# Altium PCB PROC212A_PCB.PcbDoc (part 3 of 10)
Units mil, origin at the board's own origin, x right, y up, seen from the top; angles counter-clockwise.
Board outline 3032.48 x 3598.78 mil, 4 copper layers (Top Layer, L2_GND1, L3_PWR1, Bottom Layer), stack 60.58 mil thick; 432 components, 310 nets, 7775 pads, 1236 vias.
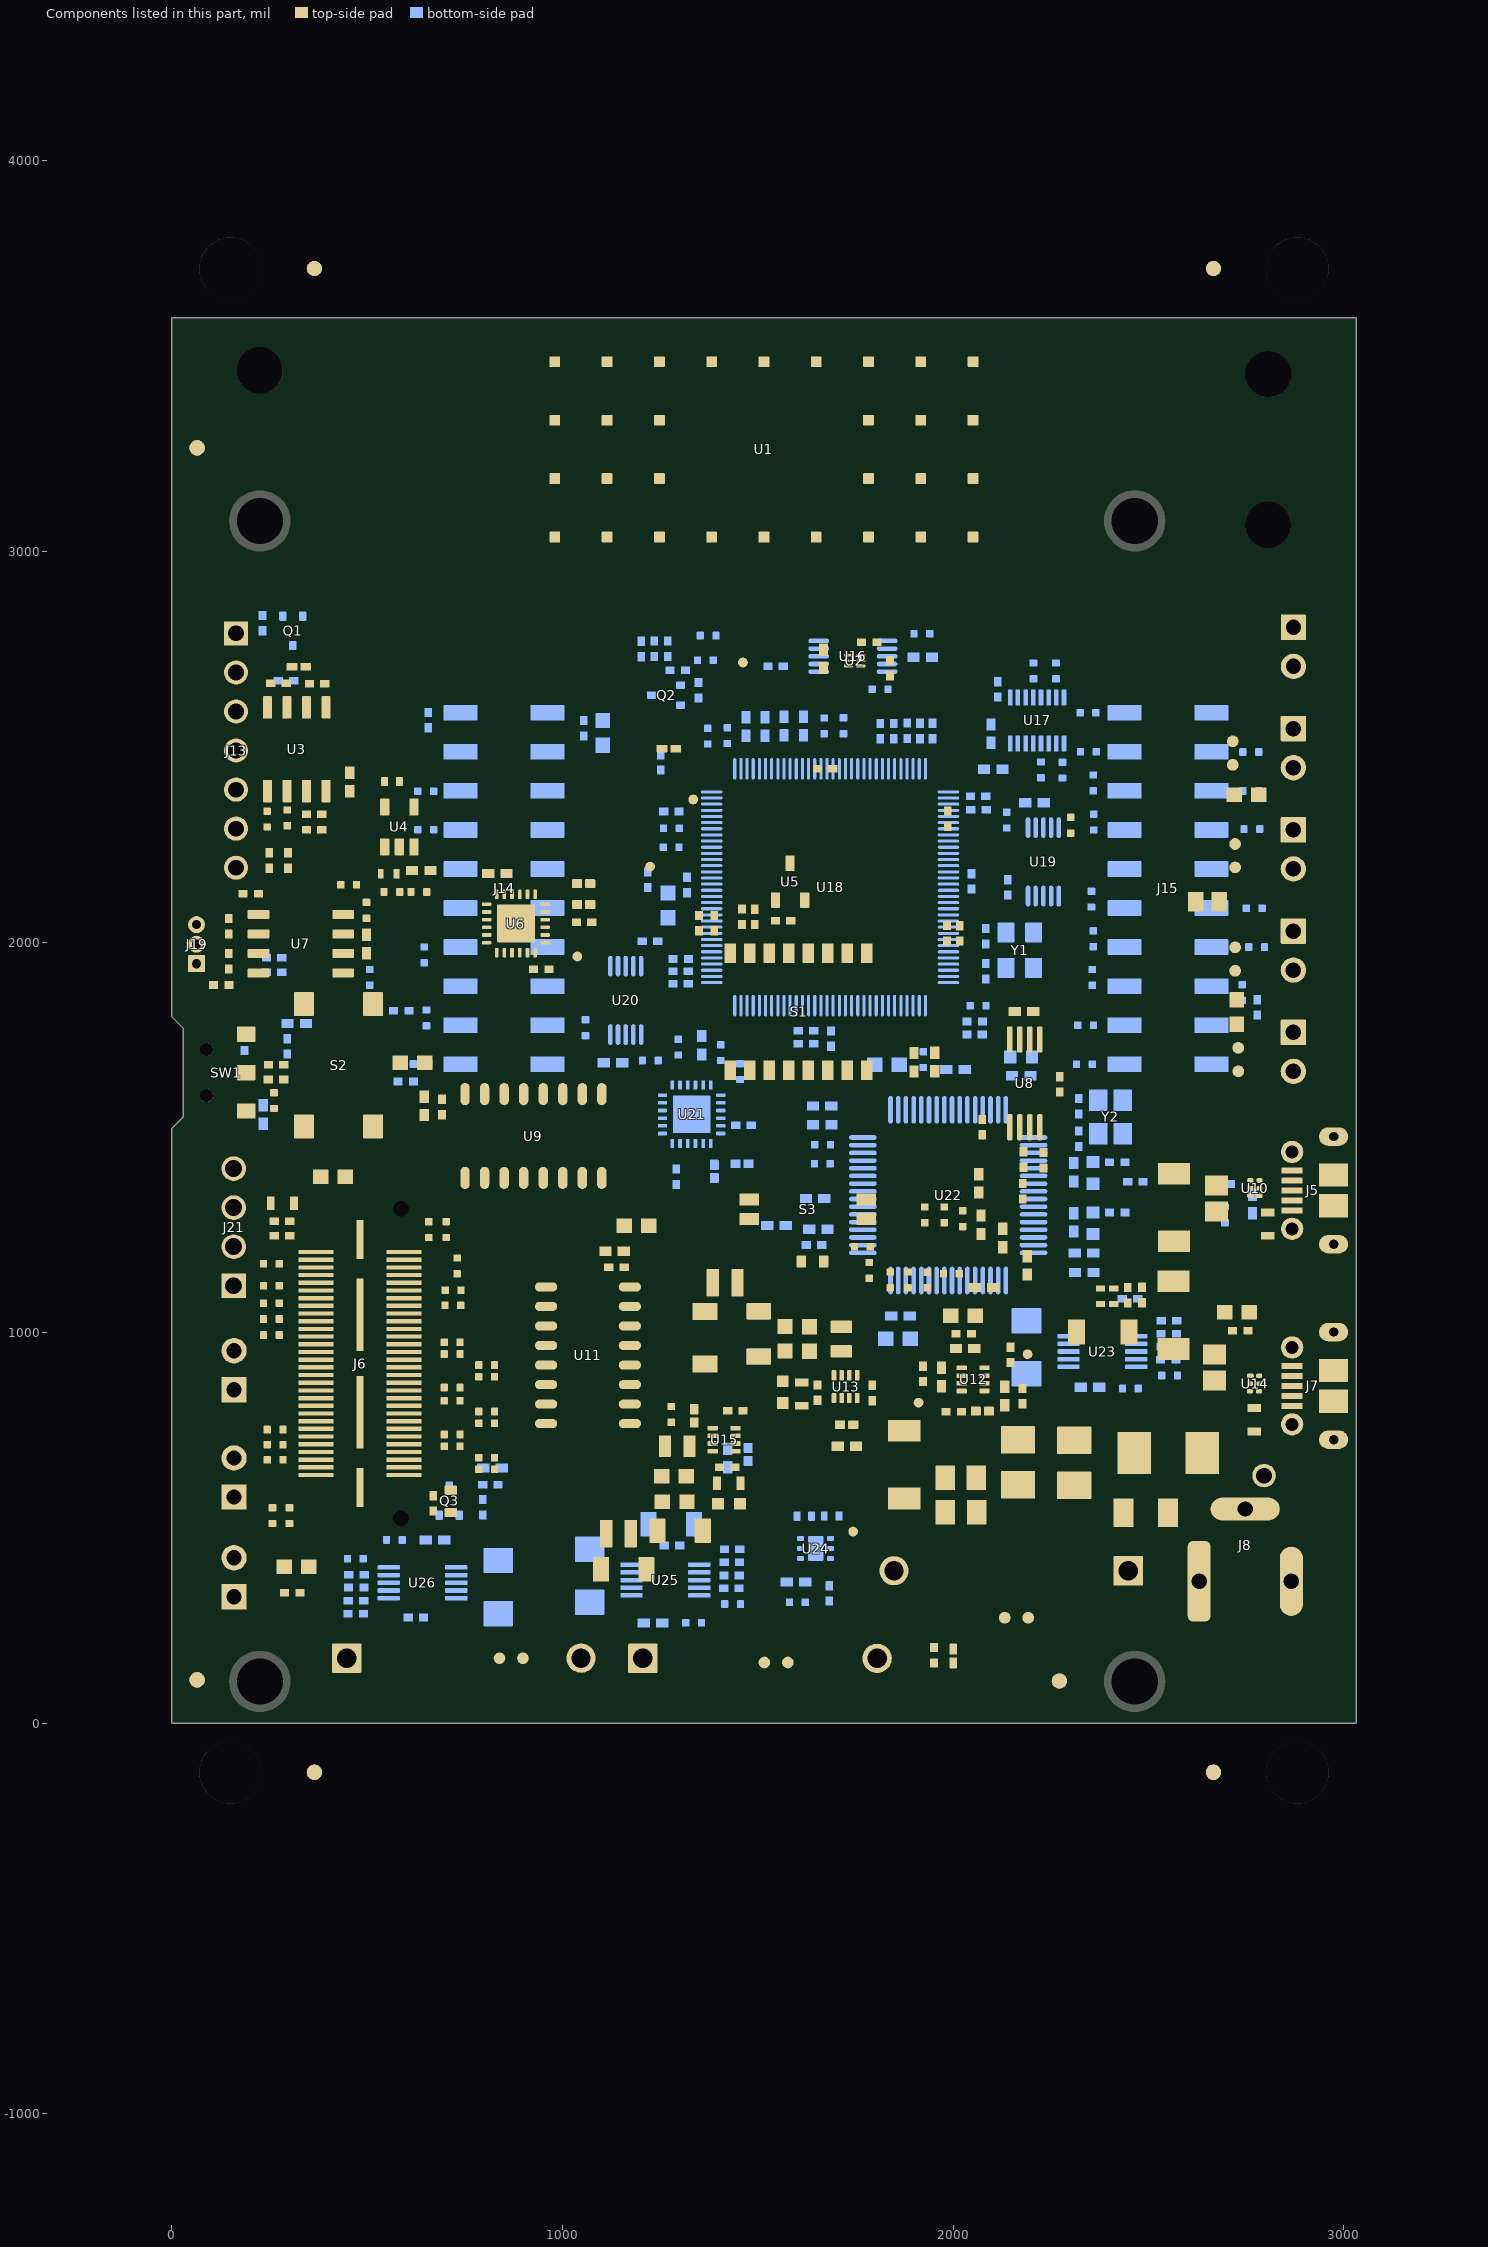
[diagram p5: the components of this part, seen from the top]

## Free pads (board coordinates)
  round 10 on Mech16: 1(-148.05,-1175.74) 1(-148.05,-1175.74) 1(431.38,4244.22) 1(431.38,4244.22) 1(878.29,1523.73) 1(892.27,1523.73) 1(2206.87,2181.52) 1(2218.29,2181.52) 1(2660.96,1519.94) 1(2677.3,1519.94) 1(2847.22,2166.22) 1(2859.23,2166.22) 1(2991.76,2275.67) 1(2991.76,2950.67) 1(3001.95,2275.67) 1(3001.95,2950.67) 1(3184.96,-1057.06) 1(3184.96,-1057.06) 1(3187.29,4244.22) 1(3187.29,4244.22) 1(3187.45,2026.76) 1(3187.45,2420.46) 1(3187.45,2701.76) 1(3187.45,3095.46)
  round 7.87 on Mech16: 1(468,1080.61) 1(468.66,1105.85) 1(471.1,4104.08) 1(471.76,4129.31) 1(483.73,1037.05) 1(484.51,1145.59) 1(486.83,4060.51) 1(487.61,4169.06) 1(495.83,1022.29) 1(498.93,4045.76) 1(501.28,1164.25) 1(504.38,4187.72) 1(533.67,998.91) 1(533.67,1182.59) 1(536.77,4022.37) 1(536.77,4206.06) 1(549.92,1186.49) 1(553.02,4209.96) 1(558.91,994.09) 1(562.01,4017.55) 1(588.92,1184.37) 1(592.02,4207.84) 1(601.85,1001.52) 1(603.6,1179.22) 1(604.95,4024.99) 1(606.7,4202.68) 1(619.13,1010.97) 1(622.23,4034.44) 1(635.23,1156.62) 1(638.32,4180.09) 1(644.83,1037.05) 1(647.93,4060.51) 1(648.12,1139.15) 1(651.22,4162.62) 1(653.51,1053.18) 1(656.61,4076.65) 1(659.91,1105.85) 1(660.97,1085.91) 1(663.01,4129.31) 1(664.07,4109.38) 1(727.72,1052.19) 1(727.72,1091.56) 1(750.23,1637.22) 1(750.23,1637.22) 1(750.23,1651.39) 1(750.23,2623.04) 1(750.23,2637.22) 1(750.23,2637.22) 1(758.45,1237.21) 1(758.45,1351.39) 1(758.45,1423.04) 1(758.45,1537.22) 1(758.45,1537.22) 1(758.99,1237.22) 1(802.52,1036.44) 1(802.52,1091.56) 1(858.45,1526.19) 1(858.45,1526.19) 1(858.45,1537.22) 1(858.45,1537.22) 1(858.45,1537.22) 1(858.99,1237.22) 1(858.99,1237.22) 1(858.99,1251.39) 1(898.56,1526.19) 1(898.56,1526.19) 1(898.56,1537.22) 1(898.56,1537.22) 1(901.43,1143.56) 1(901.43,1151.44) 1(901.43,1042.18) 1(901.43,1061.87) 1(950.23,1637.22) 1(950.23,1637.22) 1(950.23,1651.39) 1(950.23,2623.04) 1(950.23,2637.22) 1(950.23,2637.22) 1(986.08,1047.11) 1(986.08,1054.98) 1(986.08,1143.56) 1(986.08,1151.44) 1(1013.85,1228.84) 1(1013.85,1313.48) 1(1020.85,1378.89) 1(1020.85,1463.54) 1(1021.72,1228.84) 1(1021.72,1313.48) 1(1028.72,1378.89) 1(1028.72,1463.54) 1(1053.15,2495.31) 1(1053.15,2495.31) 1(1053.15,2625.23) 1(1053.15,2625.23) 1(1097.59,902.95) 1(1097.59,987.59) 1(1101.59,1083.95) 1(1101.59,1168.59) 1(1103.41,1228.84) 1(1105.46,902.95) 1(1105.46,987.59) 1(1109.46,1083.95) 1(1109.46,1168.59) 1(1110.3,1313.48) 1(1110.41,1378.89) 1(1117.3,1463.54) 1(1118.18,1313.48) 1(1123.1,1228.84) 1(1125.18,1463.54) 1(1130.1,1378.89) 1(1139.77,2495.31) 1(1139.77,2625.23) 1(1187.15,902.95) 1(1191.15,1083.95) 1(1194.04,987.59) 1(1198.04,1168.59) 1(1201.92,987.59) 1(1205.92,1168.59) 1(1206.84,902.95) 1(1210.84,1083.95) 1(1215.35,2064.09) 1(1215.35,2083.77) 1(1215.35,2083.77) 1(1234.72,1741.6) 1(1234.72,1783.92) 1(1235.74,2495.31) 1(1235.74,2625.23) 1(1246.85,2083.77) 1(1301.96,2083.77) 1(1322.35,2495.31) 1(1322.35,2495.31) 1(1322.35,2625.23) 1(1322.35,2625.23) 1(1333.46,2064.09) 1(1333.46,2083.77) 1(1333.46,2083.77) 1(1354.8,1701.25) 1(1354.8,1783.92) 1(1369.3,911.54) 1(1374.22,826.89) 1(1382.09,826.89) 1(1388.98,911.54) 1(1470.67,826.89) 1(1470.67,911.54) 1(1478.55,826.89) 1(1478.55,911.54) 1(1505.95,1970.11) 1(1505.95,1985.85) 1(1505.95,2001.6) 1(1505.95,2017.35) 1(1505.95,2033.1) 1(1505.95,2048.85) 1(1505.95,2064.59) 1(1505.95,2080.34) 1(1505.95,2096.09) 1(1505.95,2111.84) 1(1505.95,2127.59) 1(1505.95,2143.33) 1(1505.95,2159.08) 1(1505.95,2174.83) 1(1505.95,2190.58) 1(1505.95,2206.33) 1(1505.95,2222.07) 1(1505.95,2237.82) 1(1505.95,2253.57) 1(1505.95,2269.32) 1(1505.95,2285.07) 1(1505.95,2300.81) 1(1505.95,2316.56) 1(1505.95,2332.31) 1(1505.95,2348.06) 1(1505.95,2363.81) 1(1505.95,2379.55) 1(1505.95,2395.3) 1(1505.95,2411.05) 1(1505.95,2426.8) 1(1505.95,2442.55) 1(1505.95,2458.29) 1(1553.19,1970.11) 1(1553.19,1985.85) 1(1553.19,2001.6) 1(1553.19,2017.35) 1(1553.19,2033.1) 1(1553.19,2048.85) 1(1553.19,2064.59) 1(1553.19,2080.34) 1(1553.19,2096.09) 1(1553.19,2111.84) 1(1553.19,2127.59) 1(1553.19,2143.33) 1(1553.19,2159.08) 1(1553.19,2174.83) 1(1553.19,2190.58) 1(1553.19,2206.33) 1(1553.19,2222.07) 1(1553.19,2237.82) 1(1553.19,2253.57) 1(1553.19,2269.32) 1(1553.19,2285.07) 1(1553.19,2300.81) 1(1553.19,2316.56) 1(1553.19,2332.31) 1(1553.19,2348.06) 1(1553.19,2363.81) 1(1553.19,2379.55) 1(1553.19,2395.3) 1(1553.19,2411.05) 1(1553.19,2426.8) 1(1553.19,2442.55) 1(1553.19,2458.29) 1(1584.69,1966.17) 1(1584.69,1966.17) 1(1584.69,2462.23) 1(1584.69,2462.23) 1(1588.62,1887.43) 1(1588.62,1934.67) 1(1588.62,2493.73) 1(1588.62,2540.97) 1(1604.37,1887.43) 1(1604.37,1934.67) 1(1604.37,2493.73) 1(1604.37,2540.97) 1(1620.12,1887.43) 1(1620.12,1934.67) 1(1620.12,2493.73) 1(1620.12,2540.97) 1(1635.87,1887.43) 1(1635.87,1934.67) 1(1635.87,2493.73) 1(1635.87,2540.97) 1(1651.62,1887.43) 1(1651.62,1934.67) 1(1651.62,2493.73) 1(1651.62,2540.97) 1(1667.36,1887.43) 1(1667.36,1934.67) 1(1667.36,2493.73) 1(1667.36,2540.97) 1(1683.11,1887.43) 1(1683.11,1934.67) 1(1683.11,2493.73) 1(1683.11,2540.97) 1(1698.86,1887.43) 1(1698.86,1934.67) 1(1698.86,2493.73) 1(1698.86,2540.97) 1(1714.61,1887.43) 1(1714.61,1934.67) 1(1714.61,2493.73) 1(1714.61,2540.97) 1(1727.81,827.35) 1(1727.81,835.22) 1(1727.81,923.81) 1(1727.81,931.68) 1(1730.36,1887.43) 1(1730.36,1934.67) 1(1730.36,2493.73) 1(1730.36,2540.97) 1(1746.1,1887.43) 1(1746.1,1934.67) 1(1746.1,2493.73) 1(1746.1,2540.97) 1(1761.85,1887.43) 1(1761.85,1934.67) 1(1761.85,2493.73) 1(1761.85,2540.97) 1(1777.6,1887.43) 1(1777.6,1934.67) 1(1777.6,2493.73) 1(1777.6,2540.97) 1(1793.35,1887.43) 1(1793.35,1934.67) 1(1793.35,2493.73) 1(1793.35,2540.97) 1(1809.1,1887.43) 1(1809.1,1934.67) 1(1809.1,2493.73) 1(1809.1,2540.97) 1(1812.45,916.92) 1(1812.45,936.6) 1(1812.45,827.35) 1(1812.45,835.22) 1(1824.84,1887.43) 1(1824.84,1934.67) 1(1824.84,2493.73) 1(1824.84,2540.97) 1(1840.59,1887.43) 1(1840.59,1934.67) 1(1840.59,2493.73) 1(1840.59,2540.97) 1(1856.34,1887.43) 1(1856.34,1934.67) 1(1856.34,2493.73) 1(1856.34,2540.97) 1(1872.09,1887.43) 1(1872.09,1934.67) 1(1872.09,2493.73) 1(1872.09,2540.97) 1(1887.84,1887.43) 1(1887.84,1934.67) 1(1887.84,2493.73) 1(1887.84,2540.97) 1(1903.58,1887.43) 1(1903.58,1934.67) 1(1903.58,2493.73) 1(1903.58,2540.97) 1(1919.33,1887.43) 1(1919.33,1934.67) 1(1919.33,2493.73) 1(1919.33,2540.97) 1(1935.08,1887.43) 1(1935.08,1934.67) 1(1935.08,2493.73) 1(1935.08,2540.97) 1(1950.83,1887.43) 1(1950.83,1934.67) 1(1950.83,2493.73) 1(1950.83,2540.97) 1(1966.58,1887.43) 1(1966.58,1934.67) 1(1966.58,2493.73) 1(1966.58,2540.97) 1(1982.32,1887.43) 1(1982.32,1934.67) 1(1982.32,2493.73) 1(1982.32,2540.97) 1(1998.07,1887.43) 1(1998.07,1934.67) 1(1998.07,2493.73) 1(1998.07,2540.97) 1(2013.82,1887.43) 1(2013.82,1934.67) 1(2013.82,2493.73) 1(2013.82,2540.97) 1(2029.57,1887.43) 1(2029.57,1934.67) 1(2029.57,2493.73) 1(2029.57,2540.97) 1(2045.32,1887.43) 1(2045.32,1934.67) 1(2045.32,2493.73) 1(2045.32,2540.97) 1(2061.06,1887.43) 1(2061.06,1934.67) 1(2061.06,2493.73) 1(2061.06,2540.97) 1(2076.81,1887.43) 1(2076.81,1934.67) 1(2076.81,2493.73) 1(2076.81,2540.97) 1(2080.75,1966.17) 1(2080.75,1966.17) 1(2080.75,2462.23) 1(2080.75,2462.23) 1(2096.15,1494.88) 1(2112.04,1652.61) 1(2112.04,1652.61) 1(2112.04,1774.65) 1(2112.04,1774.65) 1(2112.25,1970.11) 1(2112.25,1985.85) 1(2112.25,2001.6) 1(2112.25,2017.35) 1(2112.25,2033.1) 1(2112.25,2048.85) 1(2112.25,2064.59) 1(2112.25,2080.34) 1(2112.25,2096.09) 1(2112.25,2111.84) 1(2112.25,2127.59) 1(2112.25,2143.33) 1(2112.25,2159.08) 1(2112.25,2174.83) 1(2112.25,2190.58) 1(2112.25,2206.33) 1(2112.25,2222.07) 1(2112.25,2237.82) 1(2112.25,2253.57) 1(2112.25,2269.32) 1(2112.25,2285.07) 1(2112.25,2300.81) 1(2112.25,2316.56) 1(2112.25,2332.31) 1(2112.25,2348.06) 1(2112.25,2363.81) 1(2112.25,2379.55) 1(2112.25,2395.3) 1(2112.25,2411.05) 1(2112.25,2426.8) 1(2112.25,2442.55) 1(2112.25,2458.29) 1(2154.45,358.66) 1(2159.49,1970.11) 1(2159.49,1985.85) 1(2159.49,2001.6) 1(2159.49,2017.35) 1(2159.49,2033.1) 1(2159.49,2048.85) 1(2159.49,2064.59) 1(2159.49,2080.34) 1(2159.49,2096.09) 1(2159.49,2111.84) 1(2159.49,2127.59) 1(2159.49,2143.33) 1(2159.49,2159.08) 1(2159.49,2174.83) 1(2159.49,2190.58) 1(2159.49,2206.33) 1(2159.49,2222.07) 1(2159.49,2237.82) 1(2159.49,2253.57) 1(2159.49,2269.32) 1(2159.49,2285.07) 1(2159.49,2300.81) 1(2159.49,2316.56) 1(2159.49,2332.31) 1(2159.49,2348.06) 1(2159.49,2363.81) 1(2159.49,2379.55) 1(2159.49,2395.3) 1(2159.49,2411.05) 1(2159.49,2426.8) 1(2159.49,2442.55) 1(2159.49,2458.29) 1(2165.04,1616.93) 1(2194.58,868.01) 1(2194.58,868.01) 1(2194.58,896.56) 1(2194.58,1070.77) 1(2194.58,1080.61) 1(2194.58,1080.61) 1(2204.42,1080.61) 1(2223.12,868.01) 1(2223.35,480.71) 1(2235.91,1494.88) 1(2235.91,1616.93) 1(2238.02,1652.61) 1(2238.02,1652.61) 1(2238.02,1774.65) 1(2238.02,1774.65) 1(2251.75,2395.77) 1(2251.75,2395.77) 1(2251.75,2473.27) 1(2251.75,2473.27) 1(2251.75,2493.27) 1(2251.75,2493.27) 1(2251.75,2573.27) 1(2251.75,2573.27) 1(2251.75,2593.27) 1(2251.75,2593.27) 1(2251.75,2670.77) 1(2251.75,2670.77) 1(2261.25,2383.27) 1(2261.25,2383.27) 1(2261.25,2683.27) 1(2261.25,2683.27) 1(2261.75,2483.27) 1(2261.75,2483.27) 1(2261.75,2583.27) 1(2261.75,2583.27) 1(2264.75,2383.27) 1(2264.75,2683.27) 1(2264.75,2683.27) 1(2294.22,358.66) 1(2294.22,480.71) 1(2336.75,2383.27) 1(2336.75,2683.27) 1(2336.75,2683.27) 1(2339.75,2483.27) 1(2339.75,2483.27) 1(2339.75,2583.27) 1(2339.75,2583.27) 1(2340.25,2383.27) 1(2340.25,2383.27) 1(2340.25,2683.27) 1(2340.25,2683.27) 1(2349.75,2395.77) 1(2349.75,2395.77) 1(2349.75,2473.27) 1(2349.75,2473.27) 1(2349.75,2493.27) 1(2349.75,2493.27) 1(2349.75,2573.27) 1(2349.75,2573.27) 1(2349.75,2593.27) 1(2349.75,2593.27) 1(2349.75,2670.77) 1(2349.75,2670.77) 1(2377.65,868.01) 1(2377.65,1080.61) 1(2387.49,868.01) 1(2387.49,868.01) 1(2387.49,877.85) 1(2387.49,1070.77) 1(2387.49,1080.61) 1(2387.49,1080.61) 1(2450.23,1637.22) 1(2450.23,1637.22) 1(2450.23,1651.39) 1(2450.23,2623.04) 1(2450.23,2637.22) 1(2450.23,2637.22) 1(2540.93,1237.21) 1(2540.93,1351.39) 1(2540.93,1423.04) 1(2540.93,1537.22) 1(2540.93,1537.22) 1(2541.47,1237.22) 1(2626.21,907.62) 1(2626.21,915.49) 1(2626.21,806.24) 1(2626.21,825.93) 1(2640.93,1526.19) 1(2640.93,1526.19) 1(2640.93,1537.22) 1(2640.93,1537.22) 1(2640.93,1537.22) 1(2641.47,1237.22) 1(2641.47,1237.22) 1(2641.47,1251.39) 1(2650.23,1637.22) 1(2650.23,1637.22) 1(2650.23,1651.39) 1(2650.23,2623.04) 1(2650.23,2637.22) 1(2650.23,2637.22) 1(2681.04,1526.19) 1(2681.04,1526.19) 1(2681.04,1537.22) 1(2681.04,1537.22) 1(2683.32,575.25) 1(2683.32,697.29) 1(2689.42,-639.38) 1(2689.42,-639.38) 1(2689.42,-552.77) 1(2689.42,-456.8) 1(2689.42,-370.18) 1(2689.42,-370.18) 1(2700.1,4124.08) 1(2700.76,4149.31) 1(2708,1080.61) 1(2708.66,1105.85) 1(2710.86,811.16) 1(2710.86,819.04) 1(2710.86,907.62) 1(2710.86,915.49) 1(2715.83,4080.51) 1(2716.61,4189.06) 1(2723.73,1037.05) 1(2724.51,1145.59) 1(2727.93,4065.76) 1(2733.38,4207.72) 1(2735.83,1022.29) 1(2741.28,1164.25) 1(2754.19,575.25) 1(2764.75,1780.77) 1(2764.75,1780.77) 1(2764.75,1858.27) 1(2764.75,1858.27) 1(2764.75,1878.27) 1(2764.75,1878.27) 1(2764.75,1958.27) 1(2764.75,1958.27) 1(2764.75,1978.27) 1(2764.75,1978.27) 1(2764.75,2055.77) 1(2764.75,2055.77) 1(2765.77,4042.37) 1(2765.77,4226.06) 1(2773.67,998.91) 1(2773.67,1182.59) 1(2774.25,1768.27) 1(2774.25,1768.27) 1(2774.25,2068.27) 1(2774.25,2068.27) 1(2774.75,1868.27) 1(2774.75,1868.27) 1(2774.75,1968.27) 1(2774.75,1968.27) 1(2777.75,1768.27) 1(2777.75,1768.27) 1(2777.75,2068.27) 1(2782.02,4229.96) 1(2789.92,1186.49) 1(2791.01,4037.55) 1(2798.91,994.09) 1(2819.34,-639.38) 1(2819.34,-639.38) 1(2819.34,-552.77) 1(2819.34,-456.8) 1(2819.34,-370.18) 1(2819.34,-370.18) 1(2821.02,4227.84) 1(2823.08,697.29) 1(2828.92,1184.37) 1(2833.95,4044.99) 1(2835.7,4222.68) 1(2841.85,1001.52) 1(2843.6,1179.22) 1(2849.75,1768.27) 1(2849.75,1768.27) 1(2849.75,2068.27) 1(2851.23,4054.44) 1(2852.75,1868.27) 1(2852.75,1868.27) 1(2852.75,1968.27) 1(2852.75,1968.27) 1(2853.25,1768.27) 1(2853.25,1768.27) 1(2853.25,2068.27) 1(2853.25,2068.27) 1(2853.7,2194.75) 1(2859.13,1010.97) 1(2862.75,1780.77) 1(2862.75,1780.77) 1(2862.75,1858.27) 1(2862.75,1858.27) 1(2862.75,1878.27) 1(2862.75,1878.27) 1(2862.75,1958.27) 1(2862.75,1958.27) 1(2862.75,1978.27) 1(2862.75,1978.27) 1(2862.75,2055.77) 1(2862.75,2055.77) 1(2865.51,2261.68) 1(2867.32,4200.09) 1(2875.23,1156.62) 1(2876.93,4080.51) 1(2880.22,4182.62) 1(2881.26,2194.75) 1(2881.26,2261.68) 1(2884.83,1037.05) 1(2885.61,4096.65) 1(2888.12,1139.15) 1(2892.01,4149.31) 1(2893.07,4129.38) 1(2893.51,1053.18) 1(2899.91,1105.85) 1(2900.97,1085.91)
  round 78.74 on Mech16: 1(525.05,-945.06) 1(568.38,3790.22) 1(3003.38,3861.22)
  round 7 on Mech16: 1(526.38,209.72) 1(526.38,209.72) 1(526.38,250.72) 1(526.38,250.72) 1(526.96,259.71) 1(526.96,259.71) 1(526.96,300.71) 1(526.96,300.71) 1(526.96,358.13) 1(526.96,358.13) 1(526.96,399.13) 1(526.96,399.13) 1(527.01,308.25) 1(527.01,308.25) 1(527.01,349.25) 1(527.01,349.25) 1(528.01,157.25) 1(528.01,157.25) 1(528.01,198.25) 1(528.01,198.25) 1(543.38,2101.72) 1(543.38,2101.72) 1(543.38,2142.72) 1(543.38,2142.72) 1(543.38,2150.72) 1(543.38,2150.72) 1(543.38,2191.72) 1(543.38,2191.72) 1(543.38,2052.72) 1(543.38,2052.72) 1(543.38,2093.72) 1(543.38,2093.72) 1(549.38,209.72) 1(549.38,250.72) 1(549.96,259.71) 1(549.96,300.71) 1(549.96,358.13) 1(549.96,399.13) 1(550.01,308.25) 1(550.01,349.25) 1(551.01,157.25) 1(551.01,198.25) 1(566.38,2101.72) 1(566.38,2142.72) 1(566.38,2150.72) 1(566.38,2191.72) 1(566.38,2052.72) 1(566.38,2093.72) 1(599.38,209.72) 1(599.38,250.72) 1(599.96,259.71) 1(599.96,300.71) 1(599.96,358.13) 1(599.96,399.13) 1(600.01,308.25) 1(600.01,349.25) 1(601.01,157.25) 1(601.01,198.25) 1(616.38,2101.72) 1(616.38,2142.72) 1(616.38,2150.72) 1(616.38,2191.72) 1(616.38,2052.72) 1(616.38,2093.72) 1(622.38,209.72) 1(622.38,209.72) 1(622.38,250.72) 1(622.38,250.72) 1(622.96,259.71) 1(622.96,259.71) 1(622.96,300.71) 1(622.96,300.71) 1(622.96,358.13) 1(622.96,358.13) 1(622.96,399.13) 1(622.96,399.13) 1(623.01,308.25) 1(623.01,308.25) 1(623.01,349.25) 1(623.01,349.25) 1(624.01,157.25) 1(624.01,157.25) 1(624.01,198.25) 1(624.01,198.25) 1(639.38,2101.72) 1(639.38,2101.72) 1(639.38,2142.72) 1(639.38,2142.72) 1(639.38,2150.72) 1(639.38,2150.72) 1(639.38,2191.72) 1(639.38,2191.72) 1(639.38,2052.72) 1(639.38,2052.72) 1(639.38,2093.72) 1(639.38,2093.72) 1(745.01,186.25) 1(745.01,186.25) 1(745.01,227.25) 1(745.01,227.25) 1(746.01,513.25) 1(746.01,513.25) 1(746.01,554.25) 1(746.01,554.25) 1(746.01,564.25) 1(746.01,564.25) 1(746.01,605.25) 1(746.01,605.25) 1(746.51,236.75) 1(746.51,236.75) 1(746.51,259.75) 1(746.51,309.75) 1(746.51,332.75) 1(746.51,332.75) 1(747.01,666.25) 1(747.01,666.25) 1(747.01,707.25) 1(747.01,707.25) 1(747.25,615.25) 1(747.25,615.25) 1(747.25,656.25) 1(747.25,656.25) 1(748.01,717.25) 1(748.01,717.25) 1(748.01,758.25) 1(748.01,758.25) 1(768.01,186.25) 1(768.01,227.25) 1(769.01,513.25) 1(769.01,554.25) 1(769.01,564.25) 1(769.01,605.25) 1(770.01,666.25) 1(770.01,707.25) 1(770.25,615.25) 1(770.25,656.25) 1(771.01,717.25) 1(771.01,758.25) 1(787.51,236.75) 1(787.51,236.75) 1(787.51,259.75) 1(787.51,309.75) 1(787.51,332.75) 1(787.51,332.75) 1(797.51,236.75) 1(797.51,236.75) 1(797.51,259.75) 1(797.51,309.75) 1(797.51,332.75) 1(797.51,332.75) 1(818.01,186.25) 1(818.01,227.25) 1(819.01,513.25) 1(819.01,554.25) 1(819.01,564.25) 1(819.01,605.25) 1(820.01,666.25) 1(820.01,707.25) 1(820.25,615.25) 1(820.25,656.25) 1(821.01,717.25) 1(821.01,758.25) 1(838.51,236.75) 1(838.51,236.75) 1(838.51,259.75) 1(838.51,309.75) 1(838.51,332.75) 1(838.51,332.75) 1(841.01,186.25) 1(841.01,186.25) 1(841.01,227.25) 1(841.01,227.25) 1(842.01,513.25) 1(842.01,513.25) 1(842.01,554.25) 1(842.01,554.25) 1(842.01,564.25) 1(842.01,564.25) 1(842.01,605.25) 1(842.01,605.25) 1(843.01,666.25) 1(843.01,666.25) 1(843.01,707.25) 1(843.01,707.25) 1(843.25,615.25) 1(843.25,615.25) 1(843.25,656.25) 1(843.25,656.25) 1(844.01,717.25) 1(844.01,717.25) 1(844.01,758.25) 1(844.01,758.25) 1(903.11,597.78) 1(903.11,597.78) 1(903.11,633.22) 1(903.11,751.33) 1(903.11,786.76) 1(903.11,786.76) 1(940.52,3373.78) 1(940.52,3373.78) 1(940.52,3409.22) 1(940.52,3527.33) 1(940.52,3562.76) 1(940.52,3562.76) 1(948.08,-172.06) 1(948.08,-172.06) 1(948.08,-131.06) 1(948.08,-131.06) 1(948.08,-96.19) 1(948.08,-96.19) 1(948.08,-55.19) 1(948.08,-55.19) 1(948.26,85.63) 1(948.26,85.63) 1(948.26,180.91) 1(948.26,180.91) 1(950.25,798.27) 1(950.25,798.27) 1(950.25,821.27) 1(950.25,871.27) 1(950.25,894.27) 1(950.25,894.27) 1(971.08,-172.06) 1(971.08,-131.06) 1(971.08,-96.19) 1(971.08,-55.19) 1(973.12,-46.77) 1(973.12,-46.77) 1(973.12,-20.78) 1(973.12,47.22) 1(973.12,73.2) 1(973.12,73.2) 1(977.88,-330.78) 1(977.88,-330.78) 1(977.88,-307.78) 1(977.88,-257.78) 1(977.88,-234.78) 1(977.88,-234.78) 1(983.7,85.63) 1(983.7,180.91) 1(991.25,798.27) 1(991.25,798.27) 1(991.25,821.27) 1(991.25,871.27) 1(991.25,894.27) 1(991.25,894.27) 1(998.39,597.78) 1(998.39,597.78) 1(998.39,633.22) 1(998.39,751.33) 1(998.39,786.76) 1(998.39,786.76) 1(1018.88,-330.78) 1(1018.88,-330.78) 1(1018.88,-307.78) 1(1018.88,-257.78) 1(1018.88,-234.78) 1(1018.88,-234.78) 1(1021.08,-172.06) 1(1021.08,-131.06) 1(1021.08,-96.19) 1(1021.08,-55.19) 1(1027.58,-46.77) 1(1027.58,-46.77) 1(1027.58,-20.78) 1(1027.58,47.22) 1(1027.58,73.2) 1(1027.58,73.2) 1(1027.88,-330.78) 1(1027.88,-330.78) 1(1027.88,-307.78) 1(1027.88,-257.78) 1(1027.88,-234.78) 1(1027.88,-234.78) 1(1035.79,3373.78) 1(1035.79,3373.78) 1(1035.79,3409.22) 1(1035.79,3527.33) 1(1035.79,3562.76) 1(1035.79,3562.76) 1(1044.08,-172.06) 1(1044.08,-172.06) 1(1044.08,-131.06) 1(1044.08,-131.06) 1(1044.08,-96.19) 1(1044.08,-96.19) 1(1044.08,-55.19) 1(1044.08,-55.19) 1(1068.88,-330.78) 1(1068.88,-330.78) 1(1068.88,-307.78) 1(1068.88,-257.78) 1(1068.88,-234.78) 1(1068.88,-234.78) 1(1074.01,20.25) 1(1074.01,20.25) 1(1074.01,61.25) 1(1074.01,61.25) 1(1077.76,-165.28) 1(1077.76,-165.28) 1(1077.76,-124.28) 1(1077.76,-124.28) 1(1079.07,-332.13) 1(1079.07,-332.13) 1(1079.07,-309.13) 1(1079.07,-259.13) 1(1079.07,-236.13) 1(1079.07,-236.13) 1(1082.76,-75.28) 1(1082.76,-75.28) 1(1082.76,-34.28) 1(1082.76,-34.28) 1(1097.01,20.25) 1(1097.01,61.25) 1(1100.76,-165.28) 1(1100.76,-124.28) 1(1101.81,85.63) 1(1101.81,180.91) 1(1105.76,-75.28) 1(1105.76,-34.28) 1(1120.07,-332.13) 1(1120.07,-332.13) 1(1120.07,-309.13) 1(1120.07,-259.13) 1(1120.07,-236.13) 1(1120.07,-236.13) 1(1121.37,738.77) 1(1121.37,738.77) 1(1121.37,779.77) 1(1121.37,779.77) 1(1130.75,448.77) 1(1130.75,448.77) 1(1130.75,489.77) 1(1130.75,489.77) 1(1131.75,622.77) 1(1131.75,622.77) 1(1131.75,663.77) 1(1131.75,663.77) 1(1132.13,531.77) 1(1132.13,531.77) 1(1132.13,572.77) 1(1132.13,572.77) 1(1134.07,-332.13) 1(1134.07,-332.13) 1(1134.07,-309.13) 1(1134.07,-259.13) 1(1134.07,-236.13) 1(1134.07,-236.13) 1(1137.24,85.63) 1(1137.24,85.63) 1(1137.24,180.91) 1(1137.24,180.91) 1(1144.37,738.77) 1(1144.37,779.77) 1(1147.01,20.25) 1(1147.01,61.25) 1(1150.76,-165.28) 1(1150.76,-124.28) 1(1153.75,448.77) 1(1153.75,489.77) 1(1154.75,622.77) 1(1154.75,663.77) 1(1155.11,2165.78) 1(1155.11,2165.78) 1(1155.11,2201.22) 1(1155.11,2319.33) 1(1155.11,2354.76) 1(1155.11,2354.76) 1(1155.13,531.77) 1(1155.13,572.77) 1(1155.76,-75.28) 1(1155.76,-34.28) 1(1167.01,1447.72) 1(1167.01,1447.72) 1(1167.01,1488.72) 1(1167.01,1488.72) 1(1170.01,20.25) 1(1170.01,20.25) 1(1170.01,61.25) 1(1170.01,61.25) 1(1173.38,3347.06) 1(1173.38,3347.06) 1(1173.38,3388.06) 1(1173.38,3388.06) 1(1173.38,3397.06) 1(1173.38,3397.06) 1(1173.38,3438.06) 1(1173.38,3438.06) 1(1173.38,3497.06) 1(1173.38,3497.06) 1(1173.38,3538.06) 1(1173.38,3538.06) 1(1173.38,3447.06) 1(1173.38,3447.06) 1(1173.38,3488.06) 1(1173.38,3488.06) 1(1173.76,-165.28) 1(1173.76,-165.28) 1(1173.76,-124.28) 1(1173.76,-124.28) 1(1175.07,-332.13) 1(1175.07,-332.13) 1(1175.07,-309.13) 1(1175.07,-259.13) 1(1175.07,-236.13) 1(1175.07,-236.13) 1(1178.76,-75.28) 1(1178.76,-75.28) 1(1178.76,-34.28) 1(1178.76,-34.28) 1(1190.01,1447.72) 1(1190.01,1488.72) 1(1191.64,1323.66) 1(1191.64,1323.66) 1(1191.64,1364.66) 1(1191.64,1364.66) 1(1194.37,738.77) 1(1194.37,779.77) 1(1196.38,3347.06) 1(1196.38,3388.06) 1(1196.38,3397.06) 1(1196.38,3438.06) 1(1196.38,3497.06) 1(1196.38,3538.06) 1(1196.38,3447.06) 1(1196.38,3488.06) 1(1200.25,-334.73) 1(1200.25,-334.73) 1(1200.25,-311.73) 1(1200.25,-261.73) 1(1200.25,-238.73) 1(1200.25,-238.73) 1(1203.75,448.77) 1(1203.75,489.77) 1(1204.75,622.77) 1(1204.75,663.77) 1(1205.13,531.77) 1(1205.13,572.77) 1(1214.64,1323.66) 1(1214.64,1364.66) 1(1217.37,738.77) 1(1217.37,738.77) 1(1217.37,779.77) 1(1217.37,779.77) 1(1217.99,1875.82) 1(1217.99,1948.82) 1(1217.99,1948.82) 1(1217.99,1852.82) 1(1217.99,1852.82) 1(1217.99,1925.82) 1(1226.75,448.77) 1(1226.75,448.77) 1(1226.75,489.77) 1(1226.75,489.77) 1(1227.75,622.77) 1(1227.75,622.77) 1(1227.75,663.77) 1(1227.75,663.77) 1(1228.13,531.77) 1(1228.13,531.77) 1(1228.13,572.77) 1(1228.13,572.77) 1(1230.88,1571.22) 1(1230.88,1571.22) 1(1230.88,1594.22) 1(1230.88,1644.22) 1(1230.88,1667.22) 1(1230.88,1667.22) 1(1233.13,813.77) 1(1233.13,813.77) 1(1233.13,854.77) 1(1233.13,854.77) 1(1240.01,1447.72) 1(1240.01,1488.72) 1(1241.25,-334.73) 1(1241.25,-334.73) 1(1241.25,-311.73) 1(1241.25,-261.73) 1(1241.25,-238.73) 1(1241.25,-238.73) 1(1246.38,3347.06) 1(1246.38,3388.06) 1(1246.38,3397.06) 1(1246.38,3438.06) 1(1246.38,3497.06) 1(1246.38,3538.06) 1(1246.38,3447.06) 1(1246.38,3488.06) 1(1250.39,2165.78) 1(1250.39,2165.78) 1(1250.39,2201.22) 1(1250.39,2319.33) 1(1250.39,2354.76) 1(1250.39,2354.76) 1(1256.13,813.77) 1(1256.13,854.77) 1(1258.99,1852.82) 1(1258.99,1852.82) 1(1258.99,1925.82) 1(1258.99,1875.82) 1(1258.99,1948.82) 1(1258.99,1948.82) 1(1260.25,-334.73) 1(1260.25,-334.73) 1(1260.25,-311.73) 1(1260.25,-261.73) 1(1260.25,-238.73) 1(1260.25,-238.73) 1(1263.01,1447.72) 1(1263.01,1447.72) 1(1263.01,1488.72) 1(1263.01,1488.72) 1(1264.64,1323.66) 1(1264.64,1364.66) 1(1266.98,1853.02) 1(1266.98,1853.02) 1(1266.98,1876.02) 1(1266.98,1926.02) 1(1266.98,1949.02) 1(1266.98,1949.02) 1(1269.38,3347.06) 1(1269.38,3347.06) 1(1269.38,3388.06) 1(1269.38,3388.06) 1(1269.38,3397.06) 1(1269.38,3397.06) 1(1269.38,3438.06) 1(1269.38,3438.06) 1(1269.38,3497.06) 1(1269.38,3497.06) 1(1269.38,3538.06) 1(1269.38,3538.06) 1(1269.38,3447.06) 1(1269.38,3447.06) 1(1269.38,3488.06) 1(1269.38,3488.06) 1(1271.88,1571.22) 1(1271.88,1571.22) 1(1271.88,1594.22) 1(1271.88,1644.22) 1(1271.88,1667.22) 1(1271.88,1667.22) 1(1287.64,1323.66) 1(1287.64,1323.66) 1(1287.64,1364.66) 1(1287.64,1364.66) 1(1296.75,761.77) 1(1296.75,761.77) 1(1296.75,802.77) 1(1296.75,802.77) 1(1301.25,-334.73) 1(1301.25,-334.73) 1(1301.25,-311.73) 1(1301.25,-261.73) 1(1301.25,-238.73) 1(1301.25,-238.73) 1(1304.49,1551.03) 1(1304.49,1551.03) 1(1304.49,1577.01) 1(1304.49,1645.01) 1(1304.49,1670.99) 1(1304.49,1670.99) 1(1306.13,813.77) 1(1306.13,854.77) 1(1307.98,1853.02) 1(1307.98,1853.02) 1(1307.98,1876.02) 1(1307.98,1926.02) 1(1307.98,1949.02) 1(1307.98,1949.02) 1(1316.55,1849.23) 1(1316.55,1849.23) 1(1316.55,1875.22) 1(1316.55,1943.22) 1(1316.55,1969.2) 1(1316.55,1969.2) 1(1319.75,761.77) 1(1319.75,802.77) 1(1329.13,813.77) 1(1329.13,813.77) 1(1329.13,854.77) 1(1329.13,854.77) 1(1358.95,1551.03) 1(1358.95,1551.03) 1(1358.95,1577.01) 1(1358.95,1645.01) 1(1358.95,1670.99) 1(1358.95,1670.99) 1(1359.75,2322.77) 1(1359.75,2322.77) 1(1359.75,2363.77) 1(1359.75,2363.77) 1(1360.23,2222.87) 1(1360.23,2222.87) 1(1360.23,2263.87) 1(1360.23,2263.87) 1(1360.25,-331.11) 1(1360.25,-331.11) 1(1360.25,-308.11) 1(1360.25,-258.11) 1(1360.25,-235.11) 1(1360.25,-235.11) 1(1360.75,2272.77) 1(1360.75,2272.77) 1(1360.75,2313.77) 1(1360.75,2313.77) 1(1369.75,761.77) 1(1369.75,802.77) 1(1371.02,1849.23) 1(1371.02,1849.23) 1(1371.02,1875.22) 1(1371.02,1943.22) 1(1371.02,1969.2) 1(1371.02,1969.2) 1(1382.75,2322.77) 1(1382.75,2363.77) 1(1383.23,2222.87) 1(1383.23,2263.87) 1(1383.75,2272.77) 1(1383.75,2313.77) 1(1392.75,761.77) 1(1392.75,761.77) 1(1392.75,802.77) 1(1392.75,802.77) 1(1396.49,584.29) 1(1396.49,584.29) 1(1396.49,610.27) 1(1396.49,678.27) 1(1396.49,704.25) 1(1396.49,704.25) 1(1401.25,-331.11) 1(1401.25,-331.11) 1(1401.25,-308.11) 1(1401.25,-258.11) 1(1401.25,-235.11) 1(1401.25,-235.11) 1(1415.25,-331.11) 1(1415.25,-331.11) 1(1415.25,-308.11) 1(1415.25,-258.11) 1(1415.25,-235.11) 1(1415.25,-235.11) 1(1432.75,2322.77) 1(1432.75,2363.77) 1(1433.23,2222.87) 1(1433.23,2263.87) 1(1433.75,2272.77) 1(1433.75,2313.77) 1(1450.95,584.29) 1(1450.95,584.29) 1(1450.95,610.27) 1(1450.95,678.27) 1(1450.95,704.25) 1(1450.95,704.25) 1(1451.75,2546.77) 1(1451.75,2546.77) 1(1451.75,2587.77) 1(1451.75,2587.77) 1(1451.75,2596.77) 1(1451.75,2596.77) 1(1451.75,2637.77) 1(1451.75,2637.77) 1(1455.75,2322.77) 1(1455.75,2322.77) 1(1455.75,2363.77) 1(1455.75,2363.77) 1(1456.23,2222.87) 1(1456.23,2222.87) 1(1456.23,2263.87) 1(1456.23,2263.87) 1(1456.25,-331.11) 1(1456.25,-331.11) 1(1456.25,-308.11) 1(1456.25,-258.11) 1(1456.25,-235.11) 1(1456.25,-235.11) 1(1456.75,2272.77) 1(1456.75,2272.77) 1(1456.75,2313.77) 1(1456.75,2313.77) 1(1468.03,-332.13) 1(1468.03,-332.13) 1(1468.03,-309.13) 1(1468.03,-259.13) 1(1468.03,-236.13) 1(1468.03,-236.13) 1(1474.75,2546.77) 1(1474.75,2587.77) 1(1474.75,2596.77) 1(1474.75,2637.77) 1(1478.53,682.93) 1(1478.53,682.93) 1(1478.53,737.39) 1(1478.53,737.39) 1(1504.51,682.93) 1(1504.51,737.39) 1(1509.03,-332.13) 1(1509.03,-332.13) 1(1509.03,-309.13) 1(1509.03,-259.13) 1(1509.03,-236.13) 1(1509.03,-236.13) 1(1524.75,2546.77) 1(1524.75,2587.77) 1(1524.75,2596.77) 1(1524.75,2637.77) 1(1528.75,-184.23) 1(1528.75,-184.23) 1(1528.75,-143.23) 1(1528.75,-143.23) 1(1547.75,2546.77) 1(1547.75,2546.77) 1(1547.75,2587.77) 1(1547.75,2587.77) 1(1547.75,2596.77) 1(1547.75,2596.77) 1(1547.75,2637.77) 1(1547.75,2637.77) 1(1549.75,-339.43) 1(1549.75,-339.43) 1(1549.75,-298.43) 1(1549.75,-298.43) 1(1549.75,-289.23) 1(1549.75,-289.23) 1(1549.75,-248.23) 1(1549.75,-248.23) 1(1551.75,-184.23) 1(1551.75,-143.23) 1(1568.13,1692.77) 1(1568.13,1692.77) 1(1568.13,1733.77) 1(1568.13,1733.77) 1(1572.51,682.93) 1(1572.51,737.39) 1(1572.75,-339.43) 1(1572.75,-298.43) 1(1572.75,-289.23) 1(1572.75,-248.23) 1(1585.13,890.77) 1(1585.13,890.77) 1(1585.13,931.77) 1(1585.13,931.77) 1(1591.13,1692.77) 1(1591.13,1733.77) 1(1598.49,682.93) 1(1598.49,682.93) 1(1598.49,737.39) 1(1598.49,737.39) 1(1601.75,-184.23) 1(1601.75,-143.23) 1(1608.13,890.77) 1(1608.13,931.77) 1(1621.37,2588.6) 1(1621.37,2588.6) 1(1621.37,2611.6) 1(1621.37,2661.6) 1(1621.37,2684.6) 1(1621.37,2684.6) 1(1622.75,-339.43) 1(1622.75,-298.43) 1(1622.75,-289.23) 1(1622.75,-248.23) 1(1624.75,-184.23) 1(1624.75,-184.23) 1(1624.75,-143.23) 1(1624.75,-143.23) 1(1630.88,1517.59) 1(1630.88,1517.59) 1(1630.88,1540.59) 1(1630.88,1590.59) 1(1630.88,1613.59) 1(1630.88,1613.59) 1(1641.13,1692.77) 1(1641.13,1733.77) 1(1645.75,-339.43) 1(1645.75,-339.43) 1(1645.75,-298.43) 1(1645.75,-298.43) 1(1645.75,-289.23) 1(1645.75,-289.23) 1(1645.75,-248.23) 1(1645.75,-248.23) 1(1650.19,467.49) 1(1650.19,467.49) 1(1650.19,508.49) 1(1650.19,508.49) 1(1657.69,519.99) 1(1657.69,519.99) 1(1657.69,542.99) 1(1657.69,592.99) 1(1657.69,615.99) 1(1657.69,615.99) 1(1658.13,890.77) 1(1658.13,931.77) 1(1662.37,2588.6) 1(1662.37,2588.6) 1(1662.37,2611.6) 1(1662.37,2661.6) 1(1662.37,2684.6) 1(1662.37,2684.6) 1(1664.13,1692.77) 1(1664.13,1692.77) 1(1664.13,1733.77) 1(1664.13,1733.77) 1(1664.75,977.77) 1(1664.75,977.77) 1(1664.75,1018.77) 1(1664.75,1018.77) 1(1671.88,1517.59) 1(1671.88,1517.59) 1(1671.88,1540.59) 1(1671.88,1590.59) 1(1671.88,1613.59) 1(1671.88,1613.59) 1(1673.19,467.49) 1(1673.19,508.49) 1(1681.13,890.77) 1(1681.13,890.77) 1(1681.13,931.77) 1(1681.13,931.77) 1(1686.39,1547.4) 1(1686.39,1547.4) 1(1686.39,1570.4) 1(1686.39,1620.4) 1(1686.39,1643.4) 1(1686.39,1643.4) 1(1686.39,1652.4) 1(1686.39,1652.4) 1(1686.39,1675.4) 1(1686.39,1725.4) 1(1686.39,1748.4) 1(1686.39,1748.4) 1(1687.75,977.77) 1(1687.75,1018.77) 1(1688.37,-339.43) 1(1688.37,-339.43) 1(1688.37,-298.43) 1(1688.37,-298.43) 1(1693.75,1341.77) 1(1693.75,1341.77) 1(1693.75,1382.77) 1(1693.75,1382.77) 1(1698.69,519.99) 1(1698.69,519.99) 1(1698.69,542.99) 1(1698.69,592.99) 1(1698.69,615.99) 1(1698.69,615.99) 1(1711.37,-339.43) 1(1711.37,-298.43) 1(1712.69,519.99) 1(1712.69,519.99) 1(1712.69,542.99) 1(1712.69,592.99) 1(1712.69,615.99) 1(1712.69,615.99) 1(1716.75,1341.77) 1(1716.75,1382.77) 1(1723.19,467.49) 1(1723.19,508.49) 1(1727.17,-292.23) 1(1727.17,-292.23) 1(1727.17,-251.23) 1(1727.17,-251.23) 1(1727.39,1547.4) 1(1727.39,1547.4) 1(1727.39,1570.4) 1(1727.39,1620.4) 1(1727.39,1643.4) 1(1727.39,1643.4) 1(1727.39,1652.4) 1(1727.39,1652.4) 1(1727.39,1675.4) 1(1727.39,1725.4) 1(1727.39,1748.4) 1(1727.39,1748.4) 1(1737.75,977.77) 1(1737.75,1018.77) 1(1743.38,1143.72) 1(1743.38,1143.72) 1(1743.38,1184.72) 1(1743.38,1184.72) 1(1743.38,1208.72) 1(1743.38,1208.72) 1(1743.38,1249.72) 1(1743.38,1249.72) 1(1746.19,467.49) 1(1746.19,467.49) 1(1746.19,508.49) 1(1746.19,508.49) 1(1750.17,-292.23) 1(1750.17,-251.23) 1(1750.74,2565.8) 1(1750.74,2565.8) 1(1750.74,2588.8) 1(1750.74,2638.8) 1(1750.74,2661.8) 1(1750.74,2661.8) 1(1753.69,519.99) 1(1753.69,519.99) 1(1753.69,542.99) 1(1753.69,592.99) 1(1753.69,615.99) 1(1753.69,615.99) 1(1760.75,977.77) 1(1760.75,977.77) 1(1760.75,1018.77) 1(1760.75,1018.77) 1(1761.37,-339.43) 1(1761.37,-298.43) 1(1766.38,1143.72) 1(1766.38,1184.72) 1(1766.38,1208.72) 1(1766.38,1249.72) 1(1766.75,1341.77) 1(1766.75,1382.77) 1(1784.37,-339.43) 1(1784.37,-339.43) 1(1784.37,-298.43) 1(1784.37,-298.43) 1(1789.75,1341.77) 1(1789.75,1341.77) 1(1789.75,1382.77) 1(1789.75,1382.77) 1(1791.74,2565.8) 1(1791.74,2565.8) 1(1791.74,2588.8) 1(1791.74,2638.8) 1(1791.74,2661.8) 1(1791.74,2661.8) 1(1800.17,-292.23) 1(1800.17,-251.23) 1(1802.34,-341.46) 1(1802.34,-341.46) 1(1802.34,-300.46) 1(1802.34,-300.46) 1(1810.88,1547.4) 1(1810.88,1547.4) 1(1810.88,1570.4) 1(1810.88,1620.4) 1(1810.88,1643.4) 1(1810.88,1643.4) 1(1811.16,1652.4) 1(1811.16,1652.4) 1(1811.16,1675.4) 1(1811.16,1725.4) 1(1811.16,1748.4) 1(1811.16,1748.4) 1(1816.38,1143.72) 1(1816.38,1184.72) 1(1816.38,1208.72) 1(1816.38,1249.72) 1(1823.17,-292.23) 1(1823.17,-292.23) 1(1823.17,-251.23) 1(1823.17,-251.23) 1(1825.34,-341.46) 1(1825.34,-300.46) 1(1832.25,1756.27) 1(1832.25,1756.27) 1(1832.25,1779.27) 1(1832.25,1829.27) 1(1832.25,1852.27) 1(1832.25,1852.27) 1(1833.38,980.72) 1(1833.38,980.72) 1(1833.38,1021.72) 1(1833.38,1021.72) 1(1838.97,1053.96) 1(1838.97,1053.96) 1(1838.97,1094.96) 1(1838.97,1094.96) 1(1839.38,1143.72) 1(1839.38,1143.72) 1(1839.38,1184.72) 1(1839.38,1184.72) 1(1839.38,1208.72) 1(1839.38,1208.72) 1(1839.38,1249.72) 1(1839.38,1249.72) 1(1840.64,424.84) 1(1840.64,424.84) 1(1840.64,465.84) 1(1840.64,465.84) 1(1841.55,522.99) 1(1841.55,522.99) 1(1841.55,563.99) 1(1841.55,563.99) 1(1841.55,572.99) 1(1841.55,572.99) 1(1841.55,613.99) 1(1841.55,613.99) 1(1841.55,472.99) 1(1841.55,472.99) 1(1841.55,513.99) 1(1841.55,513.99) 1(1841.55,622.99) 1(1841.55,622.99) 1(1841.55,663.99) 1(1841.55,663.99) 1(1851.88,1547.4) 1(1851.88,1547.4) 1(1851.88,1570.4) 1(1851.88,1620.4) 1(1851.88,1643.4) 1(1851.88,1643.4) 1(1852.16,1652.4) 1(1852.16,1652.4) 1(1852.16,1675.4) 1(1852.16,1725.4) 1(1852.16,1748.4) 1(1852.16,1748.4) 1(1856.38,980.72) 1(1856.38,1021.72) 1(1861.97,1053.96) 1(1861.97,1094.96) 1(1863.64,424.84) 1(1863.64,465.84) 1(1864.55,522.99) 1(1864.55,563.99) 1(1864.55,572.99) 1(1864.55,613.99) 1(1864.55,472.99) 1(1864.55,513.99) 1(1864.55,622.99) 1(1864.55,663.99) 1(1873.25,1756.27) 1(1873.25,1756.27) 1(1873.25,1779.27) 1(1873.25,1829.27) 1(1873.25,1852.27) 1(1873.25,1852.27) 1(1875.34,-341.46) 1(1875.34,-300.46) 1(1882.75,1798.77) 1(1882.75,1798.77) 1(1882.75,1839.77) 1(1882.75,1839.77) 1(1898.34,-341.46) 1(1898.34,-341.46) 1(1898.34,-300.46) 1(1898.34,-300.46) 1(1903.31,1523.59) 1(1903.31,1523.59) 1(1903.31,1564.59) 1(1903.31,1564.59) 1(1903.42,1456.85) 1(1903.42,1456.85) 1(1903.42,1497.85) 1(1903.42,1497.85) 1(1905.75,1798.77) 1(1905.75,1839.77) 1(1906.38,980.72) 1(1906.38,1021.72) 1(1911.97,1053.96) 1(1911.97,1094.96) 1(1913.64,424.84) 1(1913.64,465.84) 1(1914.55,522.99) 1(1914.55,563.99) 1(1914.55,572.99) 1(1914.55,613.99) 1(1914.55,472.99) 1(1914.55,513.99) 1(1914.55,622.99) 1(1914.55,663.99) 1(1926.31,1523.59) 1(1926.31,1564.59) 1(1926.42,1456.85) 1(1926.42,1497.85) 1(1929.38,980.72) 1(1929.38,980.72) 1(1929.38,1021.72) 1(1929.38,1021.72) 1(1934.97,1053.96) 1(1934.97,1053.96) 1(1934.97,1094.96) 1(1934.97,1094.96) 1(1936.64,424.84) 1(1936.64,424.84) 1(1936.64,465.84) 1(1936.64,465.84) 1(1937.55,522.99) 1(1937.55,522.99) 1(1937.55,563.99) 1(1937.55,563.99) 1(1937.55,572.99) 1(1937.55,572.99) 1(1937.55,613.99) 1(1937.55,613.99) 1(1937.55,472.99) 1(1937.55,472.99) 1(1937.55,513.99) 1(1937.55,513.99) 1(1937.55,622.99) 1(1937.55,622.99) 1(1937.55,663.99) 1(1937.55,663.99) 1(1941.23,-347.23) 1(1941.23,-347.23) 1(1941.23,-306.23) 1(1941.23,-306.23) 1(1947.69,524.99) 1(1947.69,524.99) 1(1947.69,547.99) 1(1947.69,597.99) 1(1947.69,620.99) 1(1947.69,620.99) 1(1955.75,1798.77) 1(1955.75,1839.77) 1(1964.23,-347.23) 1(1964.23,-306.23) 1(1976.31,1523.59) 1(1976.31,1564.59) 1(1976.42,1456.85) 1(1976.42,1497.85) 1(1978.75,1798.77) 1(1978.75,1798.77) 1(1978.75,1839.77) 1(1978.75,1839.77) 1(1988.69,524.99) 1(1988.69,524.99) 1(1988.69,547.99) 1(1988.69,597.99) 1(1988.69,620.99) 1(1988.69,620.99) 1(1998.16,1340.37) 1(1998.16,1340.37) 1(1998.16,1435.65) 1(1998.16,1435.65) 1(1999.31,1523.59) 1(1999.31,1523.59) 1(1999.31,1564.59) 1(1999.31,1564.59) 1(1999.42,1456.85) 1(1999.42,1456.85) 1(1999.42,1497.85) 1(1999.42,1497.85) 1(2008.98,502.67) 1(2008.98,502.67) 1(2008.98,597.95) 1(2008.98,597.95) 1(2014.23,-347.23) 1(2014.23,-306.23) 1(2033.59,1340.37) 1(2033.59,1435.65) 1(2037.23,-347.23) 1(2037.23,-347.23) 1(2037.23,-306.23) 1(2037.23,-306.23) 1(2044.41,502.67) 1(2044.41,597.95) 1(2075.01,3369.71) 1(2075.01,3369.71) 1(2075.01,3410.71) 1(2075.01,3410.71) 1(2075.01,3428.72) 1(2075.01,3428.72) 1(2075.01,3469.72) 1(2075.01,3469.72) 1(2098.01,3369.71) 1(2098.01,3410.71) 1(2098.01,3428.72) 1(2098.01,3469.72) 1(2102.39,3582.71) 1(2102.39,3582.71) 1(2102.39,3623.71) 1(2102.39,3623.71) 1(2103.39,3636.71) 1(2103.39,3636.71) 1(2103.39,3677.71) 1(2103.39,3677.71) 1(2104.01,3264.72) 1(2104.01,3264.72) 1(2104.01,3305.72) 1(2104.01,3305.72) 1(2125.39,3582.71) 1(2125.39,3623.71) 1(2126.13,3318.59) 1(2126.13,3318.59) 1(2126.13,3341.59) 1(2126.13,3414.59) 1(2126.13,3424.84) 1(2126.13,3497.84) 1(2126.13,3520.84) 1(2126.13,3520.84) 1(2126.39,3636.71) 1(2126.39,3677.71) 1(2127.01,3264.72) 1(2127.01,3305.72) 1(2142.6,735.54) 1(2142.6,735.54) 1(2142.6,775.54) 1(2142.6,775.54) 1(2142.6,815.54) 1(2142.6,815.54) 1(2142.6,1131.67) 1(2142.6,1131.67) 1(2142.6,1171.67) 1(2142.6,1171.67) 1(2142.6,1211.67) 1(2142.6,1211.67) 1(2151.7,1435.65) 1(2153.51,3531.59) 1(2153.51,3531.59) 1(2153.51,3554.59) 1(2153.51,3627.59) 1(2154.13,3212.59) 1(2154.13,3212.59) 1(2154.13,3235.59) 1(2154.13,3308.59) 1(2162.52,502.67) 1(2162.52,597.95) 1(2167.13,3318.59) 1(2167.13,3318.59) 1(2167.13,3341.59) 1(2167.13,3414.59) 1(2167.13,3424.84) 1(2167.13,3497.84) 1(2167.13,3520.84) 1(2167.13,3520.84) 1(2171.01,3369.71) 1(2171.01,3410.71) 1(2171.01,3428.72) 1(2171.01,3469.72) 1(2176.39,3636.71) 1(2176.39,3677.71) 1(2176.6,735.54) 1(2176.6,815.54) 1(2176.6,1131.67) 1(2176.6,1211.67) 1(2186.87,-356.48) 1(2186.87,-356.48) 1(2186.87,-315.48) 1(2186.87,-315.48) 1(2187.14,1349.37) 1(2187.14,1435.65) 1(2187.14,1435.65) 1(2194.51,3531.59) 1(2194.51,3531.59) 1(2194.51,3554.59) 1(2194.51,3627.59) 1(2195.13,3212.59) 1(2195.13,3212.59) 1(2195.13,3235.59) 1(2195.13,3308.59) 1(2197.96,502.67) 1(2197.96,502.67) 1(2197.96,597.95) 1(2197.96,597.95) 1(2198.39,3582.71) 1(2198.39,3623.71) 1(2199.39,3636.71) 1(2199.39,3636.71) 1(2199.39,3677.71) 1(2199.39,3677.71) 1(2200.01,3264.72) 1(2200.01,3305.72) 1(2209.87,-356.48) 1(2209.87,-315.48) 1(2256.6,735.54) 1(2256.6,815.54) 1(2256.6,1131.67) 1(2256.6,1211.67) 1(2259.87,-356.48) 1(2259.87,-315.48) 1(2282.87,-356.48) 1(2282.87,-356.48) 1(2282.87,-315.48) 1(2282.87,-315.48) 1(2288.6,1131.67) 1(2288.6,1131.67) 1(2288.6,1171.67) 1(2288.6,1171.67) 1(2288.6,1211.67) 1(2288.6,1211.67) 1(2290.6,735.54) 1(2290.6,735.54) 1(2290.6,735.67) 1(2290.6,735.67) 1(2290.6,775.54) 1(2290.6,775.54) 1(2290.6,775.67) 1(2290.6,775.67) 1(2290.6,815.54) 1(2290.6,815.54) 1(2290.6,815.67) 1(2290.6,815.67) 1(2290.6,1131.67) 1(2290.6,1131.67) 1(2290.6,1171.67) 1(2290.6,1171.67) 1(2290.6,1211.67) 1(2290.6,1211.67) 1(2322.6,1131.67) 1(2322.6,1211.67) 1(2324.6,735.67) 1(2324.6,815.67) 1(2334.51,3538.22) 1(2334.51,3538.22) 1(2334.51,3561.22) 1(2334.51,3611.22) 1(2334.51,3634.22) 1(2334.51,3634.22) 1(2337.51,3059.22) 1(2337.51,3059.22) 1(2337.51,3082.22) 1(2337.51,3132.22) 1(2337.51,3155.22) 1(2337.51,3155.22) 1(2340.25,191.27) 1(2340.25,191.27) 1(2340.25,214.27) 1(2340.25,264.27) 1(2340.25,287.27) 1(2340.25,287.27) 1(2360.51,3434.59) 1(2360.51,3434.59) 1(2360.51,3457.59) 1(2360.51,3507.59) 1(2360.51,3530.59) 1(2360.51,3530.59) 1(2375.51,3538.22) 1(2375.51,3538.22) 1(2375.51,3561.22) 1(2375.51,3611.22) 1(2375.51,3634.22) 1(2375.51,3634.22) 1(2378.51,3059.22) 1(2378.51,3059.22) 1(2378.51,3082.22) 1(2378.51,3132.22) 1(2378.51,3155.22) 1(2378.51,3155.22) 1(2381.25,191.27) 1(2381.25,191.27) 1(2381.25,214.27) 1(2381.25,264.27) 1(2381.25,287.27) 1(2381.25,287.27) 1(2384,1348.67) 1(2384,1348.67) 1(2384,1537.65) 1(2384,1537.65) 1(2384,1384.11) 1(2384,1502.22) 1(2390.11,496.04) 1(2390.11,496.04) 1(2390.11,591.31) 1(2390.11,591.31) 1(2401.51,3434.59) 1(2401.51,3434.59) 1(2401.51,3457.59) 1(2401.51,3507.59) 1(2401.51,3530.59) 1(2401.51,3530.59) 1(2402.6,1131.67) 1(2402.6,1211.67) 1(2404.25,191.27) 1(2404.25,191.27) 1(2404.25,214.27) 1(2404.25,264.27) 1(2404.25,287.27) 1(2404.25,287.27) 1(2404.6,735.67) 1(2404.6,815.67) 1(2425.55,496.04) 1(2425.55,591.31) 1(2436.6,1131.67) 1(2436.6,1131.67) 1(2436.6,1171.67) 1(2436.6,1171.67) 1(2436.6,1211.67) 1(2436.6,1211.67) 1(2438.6,735.67) 1(2438.6,735.67) 1(2438.6,775.67) 1(2438.6,775.67) 1(2438.6,815.67) 1(2438.6,815.67) 1(2445.25,191.27) 1(2445.25,191.27) 1(2445.25,214.27) 1(2445.25,264.27) 1(2445.25,287.27) 1(2445.25,287.27) 1(2452.39,3481.71) 1(2452.39,3481.71) 1(2452.39,3491.71) 1(2452.39,3491.71) 1(2452.39,3532.71) 1(2452.39,3532.71) 1(2452.39,3440.71) 1(2452.39,3440.71) 1(2470.05,-1026.56) 1(2470.05,-1026.56) 1(2470.05,-1017.57) 1(2470.05,-878.56) 1(2470.05,-869.56) 1(2470.05,-869.56) 1(2473.39,3116.76) 1(2473.39,3116.76) 1(2473.39,3157.76) 1(2473.39,3157.76) 1(2473.39,3065.71) 1(2473.39,3065.71) 1(2473.39,3106.71) 1(2473.39,3106.71) 1(2473.39,3174.75) 1(2473.39,3174.75) 1(2473.39,3215.75) 1(2473.39,3215.75) 1(2474.01,3224.72) 1(2474.01,3224.72) 1(2474.01,3265.72) 1(2474.01,3265.72) 1(2475.01,3274.72) 1(2475.01,3274.72) 1(2475.01,3315.72) 1(2475.01,3315.72) 1(2475.39,3440.71) 1(2475.39,3481.71) 1(2475.39,3491.71) 1(2475.39,3532.71) 1(2479.28,1502.22) 1(2479.28,1348.67) 1(2479.28,1348.67) 1(2479.28,1537.65) 1(2479.28,1537.65) 1(2479.28,1357.62) 1(2496.39,3116.76) 1(2496.39,3157.76) 1(2496.39,3174.75) 1(2496.39,3215.75) 1(2496.39,3065.71) 1(2496.39,3106.71) 1(2497.01,3224.72) 1(2497.01,3265.72) 1(2498.01,3274.72) 1(2498.01,3315.72) 1(2525.39,3481.71) 1(2525.39,3491.71) 1(2525.39,3532.71) 1(2525.39,3440.71) 1(2543.66,496.04) 1(2543.66,591.31) 1(2546.39,3116.76) 1(2546.39,3157.76) 1(2546.39,3065.71) 1(2546.39,3106.71) 1(2546.39,3174.75) 1(2546.39,3215.75) 1(2547.01,3224.72) 1(2547.01,3265.72) 1(2548.01,3274.72) 1(2548.01,3315.72) 1(2548.39,3440.71) 1(2548.39,3440.71) 1(2548.39,3481.71) 1(2548.39,3481.71) 1(2548.39,3491.71) 1(2548.39,3491.71) 1(2548.39,3532.71) 1(2548.39,3532.71) 1(2569.39,3116.76) 1(2569.39,3116.76) 1(2569.39,3157.76) 1(2569.39,3157.76) 1(2569.39,3174.75) 1(2569.39,3174.75) 1(2569.39,3215.75) 1(2569.39,3215.75) 1(2569.39,3065.71) 1(2569.39,3065.71) 1(2569.39,3106.71) 1(2569.39,3106.71) 1(2570.01,3224.72) 1(2570.01,3224.72) 1(2570.01,3265.72) 1(2570.01,3265.72) 1(2571.01,3274.72) 1(2571.01,3274.72) 1(2571.01,3315.72) 1(2571.01,3315.72) 1(2579.09,496.04) 1(2579.09,496.04) 1(2579.09,591.31) 1(2579.09,591.31) 1(2660.75,-800.73) 1(2660.75,-800.73) 1(2660.75,-766.73) 1(2660.75,-686.73) 1(2660.75,-652.73) 1(2660.75,-652.73) 1(2700.75,-800.73) 1(2700.75,-800.73) 1(2700.75,-652.73) 1(2700.75,-652.73) 1(2737.05,-1026.56) 1(2737.05,-869.56) 1(2740.75,-800.73) 1(2740.75,-800.73) 1(2740.75,-766.73) 1(2740.75,-686.73) 1(2740.75,-652.73) 1(2740.75,-652.73) 1(2750.75,-800.73) 1(2750.75,-800.73) 1(2750.75,-766.73) 1(2750.75,-686.73) 1(2750.75,-652.73) 1(2750.75,-652.73) 1(2790.75,-800.73) 1(2790.75,-800.73) 1(2790.75,-652.73) 1(2790.75,-652.73) 1(2806.3,3008.47) 1(2806.3,3008.47) 1(2806.3,3046.07) 1(2806.3,3106.07) 1(2806.3,3143.67) 1(2806.3,3143.67) 1(2814.75,2957.66) 1(2814.75,2957.66) 1(2814.75,2998.66) 1(2814.75,2998.66) 1(2830.75,-800.73) 1(2830.75,-800.73) 1(2830.75,-766.73) 1(2830.75,-686.73) 1(2830.75,-652.73) 1(2830.75,-652.73) 1(2830.77,2295.64) 1(2830.77,2295.64) 1(2830.77,2350.1) 1(2830.77,2350.1) 1(2837.75,2957.66) 1(2837.75,2998.66) 1(2856.75,2295.64) 1(2856.75,2350.1) 1(2867.75,2755.77) 1(2867.75,2755.77) 1(2867.75,2796.77) 1(2867.75,2796.77) 1(2878.25,1651.27) 1(2878.25,1651.27) 1(2878.25,1674.27) 1(2878.25,1724.27) 1(2878.25,1747.27) 1(2878.25,1747.27) 1(2881.8,3008.47) 1(2881.8,3008.47) 1(2881.8,3143.67) 1(2881.8,3143.67) 1(2882.5,3009.17) 1(2882.5,3009.17) 1(2882.5,3046.07) 1(2882.5,3106.07) 1(2882.5,3142.97) 1(2882.5,3142.97) 1(2887.25,1383.65) 1(2887.25,1383.65) 1(2887.25,1406.65) 1(2887.25,1456.65) 1(2887.25,1479.65) 1(2887.25,1479.65) 1(2887.75,2957.66) 1(2887.75,2998.66) 1(2890.75,2755.77) 1(2890.75,2796.77) 1(2900.75,3007.27) 1(2900.75,3007.27) 1(2900.75,3041.27) 1(2900.75,3121.27) 1(2900.75,3155.27) 1(2900.75,3155.27) 1(2902.8,2033.29) 1(2902.8,2033.29) 1(2902.8,2059.27) 1(2902.8,2127.27) 1(2902.8,2153.25) 1(2902.8,2153.25) 1(2910.75,2957.66) 1(2910.75,2957.66) 1(2910.75,2998.66) 1(2910.75,2998.66) 1(2919.25,1651.27) 1(2919.25,1651.27) 1(2919.25,1674.27) 1(2919.25,1724.27) 1(2919.25,1747.27) 1(2919.25,1747.27) 1(2924.75,2295.64) 1(2924.75,2350.1) 1(2928.25,1383.65) 1(2928.25,1383.65) 1(2928.25,1406.65) 1(2928.25,1456.65) 1(2928.25,1479.65) 1(2928.25,1479.65) 1(2940.75,2755.77) 1(2940.75,2796.77) 1(2940.75,3007.27) 1(2940.75,3007.27) 1(2940.75,3155.27) 1(2940.75,3155.27) 1(2950.73,2295.64) 1(2950.73,2295.64) 1(2950.73,2350.1) 1(2950.73,2350.1) 1(2957.27,2033.29) 1(2957.27,2033.29) 1(2957.27,2059.27) 1(2957.27,2127.27) 1(2957.27,2153.25) 1(2957.27,2153.25) 1(2963.75,2755.77) 1(2963.75,2755.77) 1(2963.75,2796.77) 1(2963.75,2796.77) 1(2980.75,3007.27) 1(2980.75,3007.27) 1(2980.75,3041.27) 1(2980.75,3121.27) 1(2980.75,3155.27) 1(2980.75,3155.27) 1(2983.58,-350.57) 1(2983.58,-350.57) 1(2983.58,-327.57) 1(2983.58,-277.57) 1(2983.58,-254.57) 1(2983.58,-254.57) 1(2993.75,3188.77) 1(2993.75,3188.77) 1(2993.75,3229.77) 1(2993.75,3229.77) 1(2998.75,3260.77) 1(2998.75,3260.77) 1(2998.75,3301.77) 1(2998.75,3301.77) 1(3016.75,3188.77) 1(3016.75,3229.77) 1(3021.75,3260.77) 1(3021.75,3301.77) 1(3022.1,2062.19) 1(3022.1,2062.19) 1(3022.1,2085.81) 1(3022.1,2361.41) 1(3022.1,2385.03) 1(3022.1,2385.03) 1(3022.1,2737.19) 1(3022.1,2737.19) 1(3022.1,2760.81) 1(3022.1,3036.41) 1(3022.1,3060.03) 1(3022.1,3060.03) 1(3024.58,-350.57) 1(3024.58,-350.57) 1(3024.58,-327.57) 1(3024.58,-277.57) 1(3024.58,-254.57) 1(3024.58,-254.57) 1(3055.25,-351.73) 1(3055.25,-351.73) 1(3055.25,-328.73) 1(3055.25,-278.73) 1(3055.25,-255.73) 1(3055.25,-255.73) 1(3066.75,3188.77) 1(3066.75,3229.77) 1(3071.75,3260.77) 1(3071.75,3301.77) 1(3085.09,2062.19) 1(3085.09,2385.03) 1(3085.09,2737.19) 1(3085.09,3060.03) 1(3089.75,3188.77) 1(3089.75,3188.77) 1(3089.75,3229.77) 1(3089.75,3229.77) 1(3094.75,3260.77) 1(3094.75,3260.77) 1(3094.75,3301.77) 1(3094.75,3301.77) 1(3096.25,-351.73) 1(3096.25,-351.73) 1(3096.25,-328.73) 1(3096.25,-278.73) 1(3096.25,-255.73) 1(3096.25,-255.73)
  round 170 on Mech16: 1(564.28,1090.75) 1(567.38,4114.22) 1(2796.38,4134.22) 1(2804.28,1090.75)
  round 50 on Mech16: 1(582.63,130.01) 1(582.63,922.53) 1(1052.8,1508.54) 1(1052.8,2301.06)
